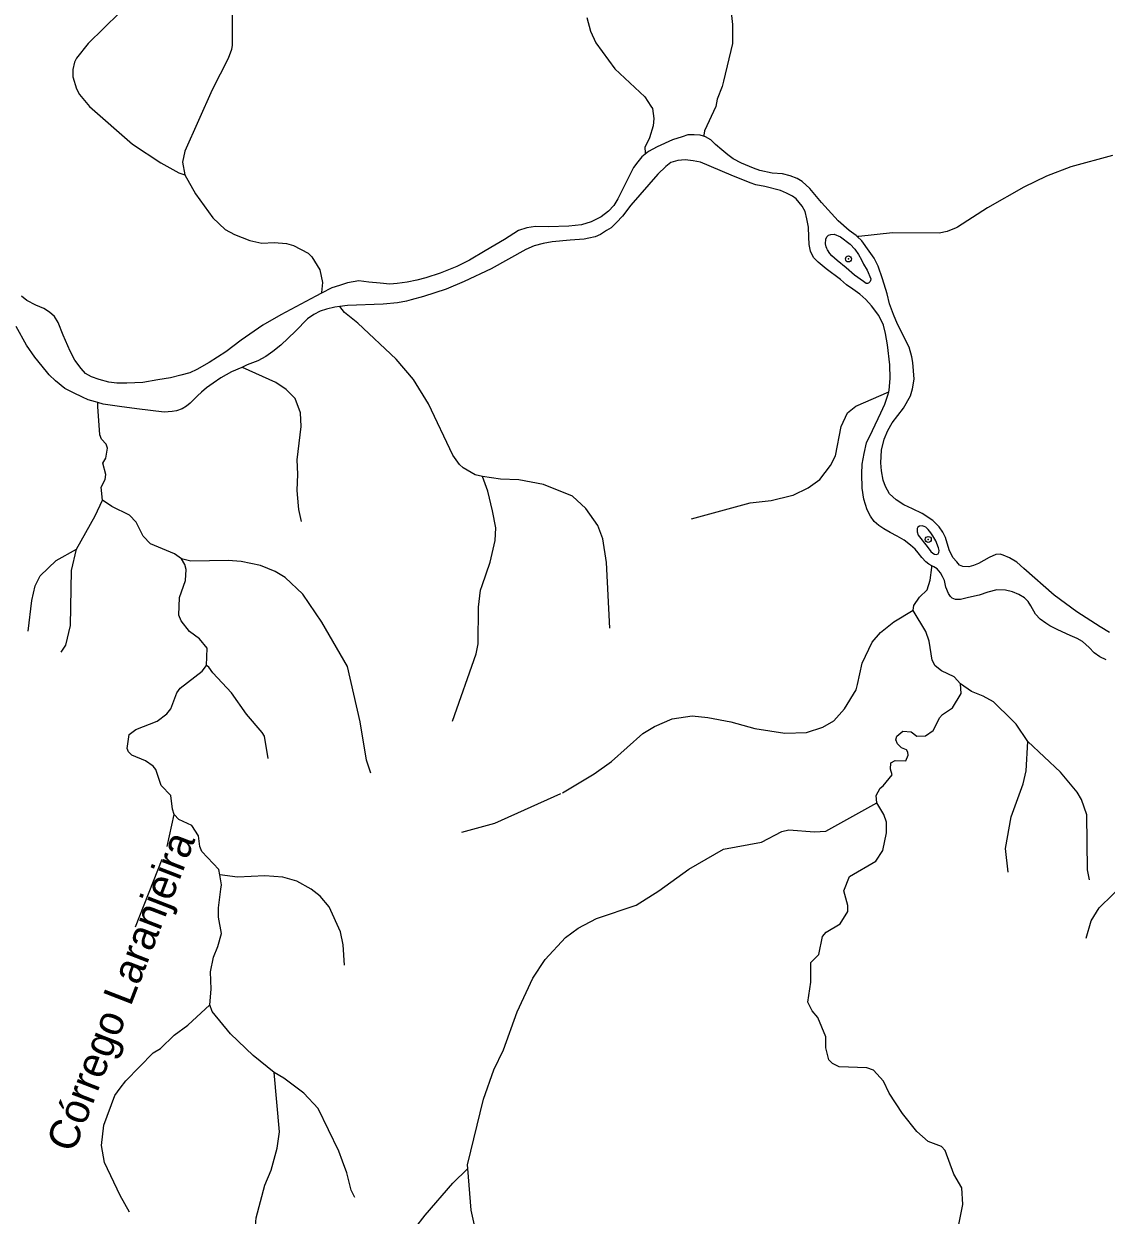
# Model space of a CAD drawing. Extents: x 393 to 446.6, y 8175.5 to 8231.
# Drawn here: x 418.78 to 424.5, y 8216.73 to 8223.04 of the extents above; entities that cross this region are included whole.
import ezdxf
from ezdxf.enums import TextEntityAlignment as Align

# ---------------------------------------------------------------- set-up
doc = ezdxf.new("R2010")
doc.units = 0
doc.header["$LTSCALE"] = 0.064
doc.header["$PDMODE"] = 32
doc.header["$PDSIZE"] = 0.032
doc.linetypes.add('LONG_DASHED', pattern=[7.5, 6, -1.5])
for name, color, linetype, lineweight in [('2', 7, 'Continuous', 25), ('7', 7, 'Continuous', 25), ('9', 7, 'LONG_DASHED', 25)]:
    doc.layers.add(name, color=color, linetype=linetype, lineweight=lineweight)
doc.layers.add('54', color=7, linetype='Continuous')
doc.layers.add('61', color=7, linetype='Continuous')

msp = doc.modelspace()

# ---------------------------------------------------------------- linework, layer by layer
at = {"layer": '2'}
for points in [[(422.3723, 8222.4414), (422.3543, 8222.4467), (422.3229, 8222.4483), (422.2899, 8222.4483), (422.2601, 8222.4384), (422.2089, 8222.4219), (422.1262, 8222.3855), (422.0816, 8222.3607), (422.0633, 8222.3459)], [(423.1859, 8221.9098), (423.1793, 8221.916), (423.1429, 8221.9424), (423.0851, 8221.9937), (422.9958, 8222.0912), (422.9346, 8222.1639), (422.895, 8222.202), (422.8668, 8222.2169), (422.8305, 8222.2317), (422.7908, 8222.2417), (422.7362, 8222.2466), (422.6701, 8222.2598), (422.637, 8222.2714), (422.5726, 8222.2979), (422.5296, 8222.321), (422.5015, 8222.3425), (422.4684, 8222.369), (422.4354, 8222.3971), (422.4106, 8222.4219), (422.3824, 8222.4384), (422.3723, 8222.4414)], [(422.0633, 8222.3459), (422.0468, 8222.3326), (422.0253, 8222.3061), (422.0022, 8222.2764), (421.9791, 8222.2301), (421.9195, 8222.1094), (421.898, 8222.0747), (421.8699, 8222.0449), (421.8303, 8222.0152), (421.7774, 8221.9887), (421.7261, 8221.9722), (421.66, 8221.9656), (421.5525, 8221.9623), (421.4831, 8221.9639), (421.4384, 8221.9573), (421.3938, 8221.9424), (421.3194, 8221.8945), (421.2169, 8221.835), (421.1342, 8221.7854), (421.0681, 8221.7523), (420.9788, 8221.7159), (420.9028, 8221.6928), (420.8548, 8221.6795), (420.8052, 8221.6696), (420.7523, 8221.6614), (420.7127, 8221.6581), (420.6614, 8221.663), (420.6019, 8221.6696), (420.549, 8221.6762), (420.4895, 8221.6647), (420.4465, 8221.6514), (420.4068, 8221.6382), (420.3517, 8221.6106)], [(423.3519, 8221.0892), (423.3539, 8221.0973), (423.3604, 8221.1591), (423.3572, 8221.2324), (423.3458, 8221.3381), (423.3344, 8221.3967), (423.3246, 8221.4407), (423.3002, 8221.4928), (423.2611, 8221.5432), (423.2318, 8221.5774), (423.1993, 8221.6051), (423.1619, 8221.6327), (423.1293, 8221.6555), (423.0968, 8221.6832), (423.0219, 8221.7402), (422.9796, 8221.7743), (422.9535, 8221.7988), (422.9389, 8221.8329), (422.9307, 8221.8687), (422.9291, 8221.9094), (422.9275, 8221.9599), (422.9193, 8222.0038), (422.9096, 8222.0429), (422.8933, 8222.0706), (422.8624, 8222.1096), (422.8429, 8222.1243), (422.8119, 8222.1406), (422.7794, 8222.1536), (422.6964, 8222.1747), (422.6492, 8222.1845), (422.6182, 8222.1943), (422.519, 8222.235), (422.3562, 8222.3033), (422.3171, 8222.3115), (422.2748, 8222.3163), (422.2358, 8222.3131), (422.1999, 8222.3017), (422.1723, 8222.2805), (422.13, 8222.2398), (421.9884, 8222.0771), (421.9428, 8222.0185), (421.9119, 8221.9843), (421.8842, 8221.9566), (421.8598, 8221.942), (421.8272, 8221.9208), (421.7996, 8221.9094), (421.7654, 8221.9013), (421.741, 8221.8964), (421.6661, 8221.8915), (421.5717, 8221.8818), (421.5245, 8221.8736), (421.4757, 8221.8606), (421.4317, 8221.8411), (421.2494, 8221.7402), (421.1062, 8221.6718), (421.0102, 8221.6327), (420.8914, 8221.5937), (420.8262, 8221.5758), (420.8002, 8221.5676), (420.753, 8221.5595), (420.6781, 8221.553), (420.4893, 8221.5449), (420.4488, 8221.5399)], [(424.5201, 8219.8147), (424.4705, 8219.8444), (424.3465, 8219.9254), (424.2275, 8220.0131), (424.0671, 8220.1536), (424.0291, 8220.1867), (423.9911, 8220.2098), (423.958, 8220.2247), (423.9415, 8220.2296), (423.9183, 8220.228), (423.8836, 8220.2115), (423.8274, 8220.18), (423.8009, 8220.1701), (423.7761, 8220.1635), (423.7447, 8220.1652), (423.7265, 8220.1718), (423.7117, 8220.1883), (423.6918, 8220.2115), (423.672, 8220.2528), (423.6521, 8220.3173), (423.6389, 8220.3454), (423.6191, 8220.3751), (423.586, 8220.4082), (423.5298, 8220.4446), (423.4786, 8220.4694), (423.4323, 8220.4909), (423.3909, 8220.5173), (423.3562, 8220.5487), (423.3347, 8220.5884), (423.3231, 8220.6215), (423.3132, 8220.6711), (423.3099, 8220.7124), (423.3132, 8220.7802), (423.3281, 8220.838), (423.3479, 8220.8843), (423.3711, 8220.924), (423.4306, 8221.0017), (423.467, 8221.0678), (423.4786, 8221.1042), (423.4868, 8221.1555), (423.4802, 8221.2431), (423.4736, 8221.2745), (423.4604, 8221.3257), (423.3992, 8221.4464), (423.3777, 8221.4977), (423.3562, 8221.5539), (423.343, 8221.6068), (423.3198, 8221.6862), (423.2967, 8221.7539), (423.2752, 8221.7953), (423.2488, 8221.8333), (423.2091, 8221.8879), (423.1859, 8221.9098)], [(420.3517, 8221.6106), (420.3208, 8221.5952), (420.1357, 8221.496), (420.0414, 8221.4415), (419.9257, 8221.3621), (419.8447, 8221.301), (419.7571, 8221.2447), (419.6926, 8221.2067), (419.6546, 8221.1885), (419.6066, 8221.177), (419.5521, 8221.1621), (419.4859, 8221.1522), (419.4066, 8221.1389), (419.3223, 8221.134), (419.2694, 8221.134), (419.2264, 8221.1406), (419.1751, 8221.1538), (419.1338, 8221.1687), (419.1024, 8221.1852), (419.0792, 8221.2117), (419.0462, 8221.2563), (419.0214, 8221.3043), (418.985, 8221.3886), (418.9586, 8221.4564), (418.9387, 8221.4878), (418.9123, 8221.5109), (418.8825, 8221.5291), (418.8395, 8221.5473), (418.7916, 8221.5721), (418.7651, 8221.5952)], [(420.4488, 8221.5399), (420.4226, 8221.5367), (420.377, 8221.5269), (420.3445, 8221.5156), (420.3103, 8221.4976), (420.2777, 8221.4749), (420.2143, 8221.4098), (420.1361, 8221.3365), (420.0938, 8221.3023), (420.0564, 8221.2763), (420.0141, 8221.2535), (419.9587, 8221.2307), (419.93, 8221.2183)], [(419.1676, 8221.0323), (419.1563, 8221.0354), (419.1173, 8221.0468), (419.0863, 8221.0598), (419.0391, 8221.0826), (418.9936, 8221.107), (418.9447, 8221.1477), (418.9106, 8221.1786), (418.8959, 8221.1965), (418.8341, 8221.273), (418.7901, 8221.3365), (418.7364, 8221.4342)], [(419.93, 8221.2183), (419.8757, 8221.1949), (419.8188, 8221.1624), (419.7781, 8221.1347), (419.7423, 8221.1103), (419.7162, 8221.0875), (419.6951, 8221.068), (419.656, 8221.0289), (419.6365, 8221.0126), (419.6137, 8220.9996), (419.5844, 8220.9882), (419.5616, 8220.985), (419.5193, 8220.9817), (419.3744, 8220.9996), (419.2833, 8221.011), (419.197, 8221.024), (419.1676, 8221.0323)], [(423.5804, 8220.1683), (423.5639, 8220.176), (423.5476, 8220.1891), (423.5264, 8220.2118), (423.5085, 8220.2363), (423.4923, 8220.2558), (423.4679, 8220.2769), (423.4337, 8220.303), (423.3962, 8220.3258), (423.3604, 8220.3437), (423.3263, 8220.3632), (423.3002, 8220.3811), (423.2758, 8220.4023), (423.2563, 8220.4299), (423.2384, 8220.4641), (423.2205, 8220.5211), (423.2107, 8220.5797), (423.2091, 8220.6546), (423.2123, 8220.7066), (423.2221, 8220.762), (423.2351, 8220.8189), (423.266, 8220.884), (423.31, 8220.9768), (423.3311, 8221.024), (423.3474, 8221.0712), (423.3519, 8221.0892)], [(424.503, 8219.6698), (424.4688, 8219.6861), (424.4395, 8219.7073), (424.4119, 8219.7366), (424.3777, 8219.7675), (424.3484, 8219.7838), (424.3126, 8219.8001), (424.2475, 8219.8294), (424.2052, 8219.8505), (424.1824, 8219.8652), (424.1531, 8219.8863), (424.1287, 8219.9124), (424.1042, 8219.9563), (424.0896, 8219.9791), (424.0701, 8219.9986), (424.0408, 8220.0165), (424.0066, 8220.0312), (423.9692, 8220.0393), (423.9236, 8220.0409), (423.8764, 8220.0279), (423.8308, 8220.0133), (423.7738, 8220.0003), (423.7315, 8219.9905), (423.7055, 8219.9905), (423.6876, 8219.997), (423.6794, 8220.0051), (423.668, 8220.0214), (423.655, 8220.0556), (423.6469, 8220.0898), (423.6371, 8220.1109), (423.6257, 8220.1305), (423.6078, 8220.1516), (423.5915, 8220.163), (423.5804, 8220.1683)]]:
    msp.add_lwpolyline(points, dxfattribs=at)
for points in [[(423.0179, 8221.8715), (423.0187, 8221.8958), (423.0249, 8221.9083), (423.0343, 8221.9169), (423.0461, 8221.9209), (423.0626, 8221.9224), (423.0963, 8221.9091), (423.1488, 8221.8699), (423.1731, 8221.8432), (423.1927, 8221.8158), (423.2084, 8221.7868), (423.2193, 8221.7648), (423.2374, 8221.7319), (423.257, 8221.6872), (423.2562, 8221.6778), (423.2531, 8221.6723), (423.2452, 8221.6637), (423.2399, 8221.6613), (423.2335, 8221.6622), (423.2193, 8221.6723), (423.1715, 8221.7068), (423.1261, 8221.7445), (423.079, 8221.7837), (423.0508, 8221.8087), (423.0406, 8221.8205), (423.0288, 8221.8393), (423.0249, 8221.8464), (423.0218, 8221.8558)], [(423.5144, 8220.3784), (423.5069, 8220.3727), (423.5031, 8220.3657), (423.5018, 8220.3581), (423.5024, 8220.348), (423.5081, 8220.3309), (423.5556, 8220.2702), (423.5745, 8220.2443), (423.5853, 8220.2348), (423.5948, 8220.2297), (423.6043, 8220.2285), (423.6131, 8220.2323), (423.6176, 8220.2392), (423.6182, 8220.2487), (423.615, 8220.2632), (423.6011, 8220.3006), (423.5859, 8220.3265), (423.5752, 8220.3417), (423.5613, 8220.36), (423.5556, 8220.3657), (423.548, 8220.3721), (423.5391, 8220.3765), (423.5284, 8220.379)]]:
    msp.add_lwpolyline(points, close=True, dxfattribs=at)
at = {"layer": '54'}
for p in [(423.139, 8221.7922), (423.5614, 8220.3075)]:
    msp.add_point(p, dxfattribs=at)
at = {"layer": '7'}
for points in [[(419.9116, 8223.4268), (419.8794, 8223.143), (419.8794, 8222.9233), (419.8746, 8222.9008), (419.8584, 8222.8523), (419.7728, 8222.6876), (419.6275, 8222.3614), (419.6162, 8222.3033), (419.6291, 8222.2373)], [(419.2825, 8223.0939), (419.1172, 8222.9314), (419.0559, 8222.8539), (419.0446, 8222.8329), (419.0365, 8222.7942), (419.0365, 8222.7555), (419.0559, 8222.6925), (419.0704, 8222.6618), (419.1237, 8222.5988), (419.3514, 8222.3986), (419.5016, 8222.3), (419.5969, 8222.2467), (419.6291, 8222.2373)], [(421.7542, 8223.0687), (421.7752, 8222.9977), (421.8026, 8222.9363), (421.9027, 8222.7974), (422.061, 8222.6505), (422.0942, 8222.6006), (422.103, 8222.5875), (422.1094, 8222.5358), (422.1062, 8222.4971), (422.0868, 8222.4325), (422.061, 8222.3808), (422.0627, 8222.3554), (422.0633, 8222.3459)], [(419.6291, 8222.2373), (419.684, 8222.137), (419.776, 8222.0094), (419.8423, 8221.948), (419.8907, 8221.9206), (419.9715, 8221.8899), (420.0361, 8221.8753), (420.1007, 8221.8786), (420.1653, 8221.8737), (420.204, 8221.8624), (420.2815, 8221.8221), (420.3009, 8221.8027), (420.3429, 8221.7349), (420.3558, 8221.6671), (420.3519, 8221.6138), (420.3517, 8221.6106)], [(421.2034, 8220.6409), (421.165, 8220.6502), (421.1002, 8220.6869), (421.0808, 8220.7047), (421.0469, 8220.7531), (420.9177, 8221.0244), (420.8386, 8221.1536), (420.7465, 8221.2618), (420.5431, 8221.4523), (420.4737, 8221.5088), (420.4488, 8221.5399)], [(420.2463, 8220.4025), (420.2312, 8220.4654), (420.2293, 8220.4859), (420.2218, 8220.5658), (420.2266, 8220.653), (420.2218, 8220.7289), (420.2444, 8220.9049), (420.2395, 8220.9775), (420.2123, 8221.0526), (420.1636, 8221.1003), (420.1104, 8221.1374), (419.9336, 8221.2167), (419.93, 8221.2183)], [(422.3083, 8220.4159), (422.6197, 8220.5012), (422.7296, 8220.5141), (422.8371, 8220.5394), (422.8458, 8220.5415), (422.9266, 8220.5803), (422.9879, 8220.6255), (423.0444, 8220.6982), (423.0702, 8220.7499), (423.1009, 8220.9049), (423.1333, 8220.9775), (423.1785, 8221.013), (423.3519, 8221.0892)], [(421.0437, 8219.3452), (421.17, 8219.7018), (421.1805, 8219.7553), (421.1825, 8219.9489), (421.1922, 8220.0394), (421.2008, 8220.0641), (421.2439, 8220.1879), (421.2697, 8220.3026), (421.273, 8220.3688), (421.2568, 8220.4592), (421.231, 8220.5626), (421.2034, 8220.6409)], [(421.8765, 8219.8382), (421.859, 8220.185), (421.8398, 8220.3106), (421.8123, 8220.3817), (421.7493, 8220.4721), (421.6783, 8220.5367), (421.5265, 8220.5981), (421.3957, 8220.6223), (421.2988, 8220.6271), (421.2034, 8220.6409)], [(424.3968, 8218.197), (424.423, 8218.2901), (424.4645, 8218.3575), (424.6102, 8218.5001), (424.6735, 8218.5743), (424.7163, 8218.6065), (424.7319, 8218.6182), (424.7833, 8218.6407), (424.8277, 8218.6691), (424.8631, 8218.7161), (424.883, 8218.7695), (424.8863, 8218.7784)]]:
    msp.add_lwpolyline(points, dxfattribs=at)
at = {"layer": '9'}
for points in [[(422.5046, 8223.2305), (422.526, 8223.0331), (422.5259, 8222.9312), (422.4782, 8222.7335), (422.4711, 8222.7039), (422.4449, 8222.6379), (422.4368, 8222.5978), (422.3781, 8222.4691), (422.3735, 8222.4472), (422.3723, 8222.4414)], [(424.5363, 8222.3386), (424.3159, 8222.2791), (424.1867, 8222.2291), (424.0667, 8222.1709), (423.874, 8222.0617), (423.7165, 8221.9604), (423.7096, 8221.9574), (423.7095, 8221.9573), (423.6616, 8221.9363), (423.6185, 8221.9286), (423.3721, 8221.9301), (423.1933, 8221.9106), (423.1859, 8221.9098)], [(419.1921, 8220.5148), (419.1855, 8220.5845), (419.2067, 8220.6249), (419.2109, 8220.6508), (419.1947, 8220.711), (419.2108, 8220.7382), (419.2189, 8220.7913), (419.2121, 8220.8116), (419.1882, 8220.8375), (419.1786, 8220.8614), (419.1689, 8221.0115), (419.1676, 8221.0323)], [(419.0545, 8220.2567), (419.1547, 8220.4325), (419.1921, 8220.5148)], [(419.6099, 8220.2046), (419.5733, 8220.2307), (419.4461, 8220.2837), (419.4084, 8220.3243), (419.3713, 8220.399), (419.3355, 8220.4363), (419.2424, 8220.4814), (419.1921, 8220.5148)], [(418.7994, 8219.8227), (418.8185, 8219.984), (418.8371, 8220.0618), (418.8623, 8220.1143), (418.948, 8220.1957), (419.0545, 8220.2567)], [(418.9741, 8219.7105), (418.9986, 8219.7489), (419.0232, 8219.8531), (419.0296, 8220.1425), (419.0545, 8220.2567)], [(419.7421, 8219.6405), (419.746, 8219.7316), (419.7052, 8219.7821), (419.6533, 8219.8201), (419.6087, 8219.8766), (419.596, 8219.9071), (419.6001, 8220.0005), (419.6322, 8220.0895), (419.6352, 8220.1478), (419.6288, 8220.1747), (419.6099, 8220.2046)], [(420.6118, 8219.071), (420.5885, 8219.1392), (420.5556, 8219.3423), (420.488, 8219.6356), (420.3539, 8219.8699), (420.2526, 8220.018), (420.1587, 8220.1054), (420.1069, 8220.1386), (420.0289, 8220.1702), (419.9258, 8220.191), (419.8573, 8220.196), (419.6594, 8220.1927), (419.6099, 8220.2046)], [(423.4815, 8219.933), (423.4844, 8219.9575), (423.5157, 8220.0016), (423.5546, 8220.0411), (423.5711, 8220.0921), (423.5793, 8220.1591), (423.5804, 8220.1683)], [(421.0934, 8218.7589), (421.2674, 8218.8057), (421.6266, 8218.9662), (421.7934, 8219.0676), (421.8852, 8219.1322), (422.0515, 8219.2799), (422.1126, 8219.3173), (422.2069, 8219.358), (422.3127, 8219.3739), (422.3956, 8219.3659), (422.5167, 8219.343), (422.643, 8219.3077), (422.8031, 8219.282), (422.9167, 8219.2868), (423.0038, 8219.3143), (423.062, 8219.3482), (423.1186, 8219.4112), (423.1799, 8219.5114), (423.1862, 8219.5397), (423.2116, 8219.6532), (423.264, 8219.7648), (423.3088, 8219.8159), (423.3785, 8219.8715), (423.4814, 8219.9329), (423.4815, 8219.933)], [(423.7311, 8219.5433), (423.6988, 8219.5806), (423.6313, 8219.613), (423.598, 8219.638), (423.5823, 8219.668), (423.5662, 8219.7699), (423.5489, 8219.8211), (423.4813, 8219.931), (423.4815, 8219.933)], [(419.5723, 8218.8524), (419.5627, 8218.8796), (419.5545, 8218.9525), (419.5023, 8219.0053), (419.4755, 8219.0898), (419.4604, 8219.108), (419.4198, 8219.1361), (419.3479, 8219.166), (419.3303, 8219.1837), (419.3226, 8219.2021), (419.3337, 8219.2751), (419.3692, 8219.3012), (419.4811, 8219.3453), (419.5327, 8219.3841), (419.555, 8219.4117), (419.5855, 8219.4965), (419.6029, 8219.5204), (419.7197, 8219.6103), (419.7421, 8219.6405)], [(420.0699, 8219.1477), (420.05, 8219.2658), (420.0372, 8219.2869), (419.9537, 8219.3838), (419.8746, 8219.4952), (419.7761, 8219.6017), (419.7551, 8219.6324), (419.7421, 8219.6405)], [(423.2896, 8218.9133), (423.2887, 8218.9147), (423.2852, 8218.9523), (423.3061, 8218.9911), (423.3235, 8219.0043), (423.3696, 8219.0626), (423.3606, 8219.0922), (423.3627, 8219.1256), (423.3855, 8219.1372), (423.4421, 8219.1368), (423.4541, 8219.1664), (423.454, 8219.1825), (423.4455, 8219.195), (423.4203, 8219.2056), (423.3978, 8219.226), (423.3901, 8219.2464), (423.3944, 8219.2667), (423.4275, 8219.2931), (423.4704, 8219.2894), (423.5002, 8219.2674), (423.5459, 8219.2675), (423.5874, 8219.2968), (423.6171, 8219.3555), (423.6215, 8219.3643), (423.6361, 8219.3812), (423.6886, 8219.417), (423.7346, 8219.492), (423.7311, 8219.5433)], [(424.0879, 8219.2385), (424.0254, 8219.3307), (424.0049, 8219.3509), (423.9055, 8219.4487), (423.8515, 8219.4789), (423.7901, 8219.5035), (423.7311, 8219.5433)], [(423.9838, 8218.5465), (423.9699, 8218.672), (424.0004, 8218.8397), (424.063, 8219.0146), (424.0795, 8219.0836), (424.0879, 8219.2385)], [(424.4139, 8218.5067), (424.4044, 8218.56), (424.3995, 8218.8504), (424.3717, 8218.931), (424.349, 8218.9703), (424.2603, 8219.0766), (424.0879, 8219.2385)], [(419.3681, 8218.2584), (419.5351, 8218.6819), (419.5723, 8218.8524)], [(419.8136, 8218.5321), (419.8086, 8218.5607), (419.7185, 8218.6559), (419.7081, 8218.6835), (419.7004, 8218.7385), (419.6656, 8218.794), (419.5968, 8218.8255), (419.5723, 8218.8524)], [(421.125, 8216.9793), (421.1235, 8216.999), (421.2084, 8217.3459), (421.2633, 8217.5009), (421.3133, 8217.6075), (421.386, 8217.8077), (421.47, 8217.9853), (421.5346, 8218.0854), (421.6428, 8218.2017), (421.709, 8218.2501), (421.8059, 8218.3018), (422.0158, 8218.3729), (422.1353, 8218.4488), (422.2952, 8218.5634), (422.4776, 8218.6684), (422.6795, 8218.7055), (422.7861, 8218.762), (422.8232, 8218.7717), (422.9589, 8218.7604), (423.0186, 8218.7637), (423.2896, 8218.9133)], [(423.708, 8216.6126), (423.7435, 8216.7876), (423.7387, 8216.8768), (423.6965, 8216.9492), (423.6515, 8217.0745), (423.6312, 8217.0958), (423.561, 8217.1226), (423.5015, 8217.1747), (423.4255, 8217.27), (423.3548, 8217.3776), (423.3247, 8217.4417), (423.2717, 8217.499), (423.2365, 8217.512), (423.0901, 8217.5171), (423.0538, 8217.5353), (423.0357, 8217.5533), (423.0202, 8217.6178), (423.02, 8217.6752), (422.9768, 8217.7778), (422.9479, 8217.8136), (422.9235, 8217.8587), (422.9392, 8217.9646), (422.9397, 8218.0689), (422.9831, 8218.1119), (423.0012, 8218.2067), (423.0218, 8218.229), (423.0957, 8218.2742), (423.1363, 8218.338), (423.1361, 8218.3708), (423.1141, 8218.4482), (423.1441, 8218.5232), (423.2847, 8218.6054), (423.32, 8218.6623), (423.3398, 8218.7546), (423.3398, 8218.8114), (423.3268, 8218.8525), (423.2896, 8218.9133)], [(419.761, 8217.8446), (419.7681, 8217.9272), (419.7648, 8218.0202), (419.7791, 8218.0975), (419.8033, 8218.1532), (419.8226, 8218.2228), (419.8066, 8218.3087), (419.8068, 8218.3579), (419.8196, 8218.4566), (419.8226, 8218.4798), (419.8136, 8218.5321)], [(420.4734, 8218.0546), (420.4662, 8218.1632), (420.4519, 8218.2319), (420.3922, 8218.3637), (420.3442, 8218.4197), (420.2966, 8218.4562), (420.2217, 8218.4987), (420.1459, 8218.5212), (420.0524, 8218.5279), (419.9068, 8218.5198), (419.8136, 8218.5321)], [(419.3363, 8216.7474), (419.2858, 8216.8362), (419.2027, 8217.0101), (419.1877, 8217.101), (419.1996, 8217.2088), (419.2578, 8217.3657), (419.2869, 8217.4043), (419.3158, 8217.4426), (419.4612, 8217.591), (419.4989, 8217.6146), (419.5715, 8217.6841), (419.6437, 8217.7368), (419.761, 8217.8446)], [(420.1013, 8217.4873), (419.9896, 8217.5763), (419.8702, 8217.6908), (419.7728, 8217.8093), (419.761, 8217.8446)], [(420.0171, 8216.425), (420.0089, 8216.4554), (419.9956, 8216.5891), (420.0054, 8216.7185), (420.0524, 8216.8903), (420.085, 8216.9702), (420.1165, 8217.0869), (420.1295, 8217.1732), (420.1013, 8217.4873)], [(420.5283, 8216.8248), (420.5084, 8216.8634), (420.4849, 8216.9557), (420.4626, 8217.0173), (420.4436, 8217.07), (420.3345, 8217.2959), (420.2582, 8217.3773), (420.1529, 8217.4567), (420.1013, 8217.4873)], [(420.7608, 8216.2199), (420.7426, 8216.4151), (420.7508, 8216.5161), (420.7745, 8216.57), (420.8999, 8216.7327), (421.0456, 8216.9016), (421.1235, 8216.9778), (421.125, 8216.9793)], [(421.3084, 8216.3101), (421.2592, 8216.3873), (421.2171, 8216.4774), (421.1867, 8216.5651), (421.1422, 8216.7581), (421.125, 8216.9793)]]:
    msp.add_lwpolyline(points, dxfattribs=at)

# ---------------------------------------------------------------- texts
at = {"layer": '61'}
msp.add_text('Córrego Laranjeira', height=0.16, rotation=68.841, dxfattribs=at).set_placement((419.3629, 8217.8884), align=Align.CENTER)

doc.saveas('drawing.dxf')
